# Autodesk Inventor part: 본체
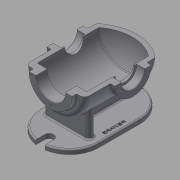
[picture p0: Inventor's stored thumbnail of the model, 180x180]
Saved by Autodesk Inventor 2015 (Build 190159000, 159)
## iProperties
Created: 2016-02
Part Number: 본체
Material: 일반
Document SubType Name: Modeling
Designer: mduedu
Density: 2.71 g/cm^3
Appearance: 기본값
Author: mduedu
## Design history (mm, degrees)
sketch "스케치2"
  geometry: L1 (0, 90)-(0, -90); L2 (65, -65.993)-(65, 90); L3 (65, 90)-(0, 90); A1 r 100 centre (0, 10) between (0, -90) and (65, -65.993); 2 further points
  constraints: 6 end point, 2 point on circle, 1 centre point, 1 coincident, 1 horizontal, 1 midpoint, 1 parallel, 1 point on line, 1 vertical
  dimensions: "d3" = 180 distance of L1.start L1.end; "d5" = 130 diameter of L2 L1; "d6" = 100 radius of A1
revolve "회전1" sketch "스케치2" stored, may be unused: angle "d7" = 90 deg
sketch "스케치3"
  geometry: C1 r 47.5 at (0, 0); 1 further point
  constraints: 1 centre point, 1 coincident
  dimensions: "d8" = 95 diameter of C1
extrude "돌출2" join sketch "스케치3" distance "d10" = 10; taper "d11" = 0 deg
sketch "스케치5"
  geometry: L1 (47.5, 100)-(47.5, 90) reference; L2 (47.5, 90)-(65, 90) reference; L3 (65, 90)-(65, -65.993) reference; L4 (-65, -65.993)-(-65, 90) reference; L5 (-65, 90)-(-47.5, 90) reference; L6 (-47.5, 90)-(-47.5, 100) reference; L7 (-47.5, 100)-(47.5, 100) reference; L8 (55, 75)-(55, -61.239); L9 (0, 75)-(55, 75); L10 (0, 75)-(0, -80); A1 r 100 centre (0, 10) between (-65, -65.993) and (0, -90) reference; A2 r 100 centre (0, 10) between (0, -90) and (65, -65.993) reference; A3 r 90 centre (0, 10) between (0, -80) and (55, -61.239); 1 further point
  constraints: 6 end point, 2 point on circle, 1 centre point, 1 parallel, 1 perpendicular, 1 point on line, 1 vertical
  dimensions: "d13" = 10 distance between parallel lines of L3 L8; "d14" = 10 radial gap between concentric circles of A3 A1; "d15" = 15 distance between parallel lines of L9 L2
revolve "회전2" sketch "스케치5" stored, may be unused: angle "d16" = 90 deg
hole "구멍1" diameter "d19" = 65; stored, may be unused: countersink angle "d23" = 90 deg, drill point angle "d25" = 118 deg; dims "d17" = 10, "d18" = 10, "d20" = 6, "d21" = 4, "d22" = 2, "d24" = 8
node "작업 평면1"
sketch "스케치6"
  geometry: L1 (47.5, 100)-(-47.5, 100) reference; C1 r 40 at (0, -7); 1 further point
  constraints: 1 centre point, 1 vertical alignment
  dimensions: "d27" = 80 diameter of C1; "d29" = 107 distance from line of C1.centre L1
extrude "돌출3" join sketch "스케치6" stored distance "d30" = 10; taper "d31" = 0 deg
hole "구멍2" diameter "d34" = 42; stored, may be unused: countersink angle "d38" = 90 deg, drill point angle "d40" = 118 deg; dims "d32" = 10, "d33" = 10, "d35" = 6, "d36" = 52, "d37" = 18, "d39" = 8
sketch "스케치7" dims "d41" = 65
  geometry: C1 r 40 at (0, 0) reference; 3 further points
  constraints: 2 vertical alignment, 1 coincident, 2 other
hole "구멍3" sketch "스케치7" at (0, 32.5) diameter "d43" = 3.242; stored, may be unused: countersink angle "d47" = 90 deg, drill point angle "d49" = 118 deg; dims "d44" = 11, "d45" = 13, "d46" = 18, "d48" = 13
sketch "스케치8" dims "d53" = 80
  geometry: 3 further points
  constraints: 2 vertical alignment, 1 coincident, 2 other
hole "구멍4" sketch "스케치8" at (0, -40) diameter "d56" = 3.242; stored, may be unused: countersink angle "d60" = 90 deg, drill point angle "d62" = 118 deg; dims "d57" = 11, "d58" = 13, "d59" = 18, "d61" = 13
fillet "모깎기1" dims "d66" = 10
fillet "모깎기2" dims "d67" = 3
fillet "모깎기3" dims "d68" = 0.3
chamfer "모따기1" distance "d69" = 1; stored, may be unused: second distance "d70" = 2, angle "d71" = 45 deg
node "작업 평면5"
sketch "스케치10"
  geometry: L1 (-50, 66)-(50, 66); L2 (50, 66)-(50, 50); L3 (50, 50)-(-50, 50); L4 (-50, 50)-(-50, 66); 2 further points
  constraints: 8 end point, 2 horizontal, 2 vertical, 1 midpoint, 1 vertical alignment
  dimensions: "d177" = 50 distance from line of L3 point (0, 0); "d178" = 100 distance of L1.start L1.end; "d179" = 16 distance of L3.end L1.start
extrude "돌출5" join sketch "스케치10" stored distance "d84" = 10; taper "d85" = 0 deg
sketch "스케치21" dims "d180" = 220, "d182" = 130
  geometry: L1 (65, 58)-(-65, 58); L2 (-65, 58)-(-65, -32); L3 (-65, -32)-(65, -32); L4 (65, -32)-(65, 58); L5 (50, 50)-(50, 66) reference; 4 further points
  constraints: 8 end point, 3 horizontal alignment, 3 midpoint, 2 parallel, 1 horizontal, 1 perpendicular, 1 vertical alignment, 4 other
extrude "돌출13" join sketch "스케치21" distance "d183" = 10; taper "d184" = 0 deg
sketch "스케치11"
  geometry: L1 (-65, 80)-(-65, -61.239) reference; L2 (-100, -97)-(-100, -32) reference; L3 (-65, -42.793)-(-100, -63); L4 (-100, -97)-(-110, -97) reference; 1 further point
  constraints: 2 end point, 2 point on line
  dimensions: "d185" = 34 distance from line of L3.end L4; "d186" = 120 deg angle of L2 L3
feature "리브1" sketch "스케치11" dims "d88" = 1, "d89" = 16, "d90" = 0, "d91" = 0, "d92" = 1, "d93" = 1
fillet "모깎기12"
fillet "모깎기13"
fillet "모깎기16" dims "d167" = 3
fillet "모깎기18"
fillet "모깎기17" dims "d168" = 3
fillet "모깎기19" dims "d187" = 3
node "작업 평면6"
sketch "스케치19"
  geometry: L1 (75, -47)-(75, 33) reference; L2 (-75, -47)-(-75, 33) reference; L3 (75, -7)-(-75, -7); C1 r 22.5 at (0, -7); 1 further point
  constraints: 3 midpoint, 2 end point, 1 centre point
  dimensions: "d149" = 45 diameter of C1
extrude "돌출11" join sketch "스케치19" stored distance "d150" = 10; taper "d151" = 0 deg
hole "구멍6" diameter "d154" = 33.376; stored, may be unused: countersink angle "d158" = 90 deg, drill point angle "d160" = 118 deg; dims "d155" = 6, "d156" = 4, "d157" = 2, "d159" = 8, "d190" = 10, "d191" = 10
fillet "모깎기11" dims "d161" = 3
chamfer "모따기3" distance "d164" = 1; stored, may be unused: second distance "d165" = 2, angle "d166" = 45 deg
node "작업 평면9"
  node "작업 평면8"
sketch "스케치22" dims "d189" = 20
  geometry: L1 (-10, -123)-(10, -123); L2 (10, -123)-(10, -103); L3 (10, -103)-(-10, -103); L4 (-10, -103)-(-10, -123); A1 r 65 centre (0, -58) between (-65, -58) and (65, -58) reference; 2 further points
  constraints: 8 end point, 2 parallel, 1 horizontal, 1 horizontal alignment, 1 midpoint, 1 perpendicular, 1 tangent, 1 vertical alignment, 2 other
  dimensions: "d193" = 30 dimension on L1
extrude "돌출14" cut sketch "스케치22" stored distance "d194" = 10; taper "d195" = 0 deg
fillet "모깎기21" dims "d196" = 3
feature "분할1"
sketch "스케치23"
  geometry: L1 (-65, 32)-(-65, -58) reference; L2 (65, -58)-(65, 32) reference; L3 (-65, -13)-(65, -13); 2 further points
  constraints: 2 end point, 2 midpoint, 1 point on line, 1 other
  dimensions: "d197" = 12 distance from line of point (53, -13) L2
feature "엠보싱2" sketch "스케치23" dims "d8" = 95, "d198" = 0.5, "d199" = 0
node "솔리드2"
pattern_circular "원형 패턴1" dims angle "d51" = 360 deg
mirror "대칭1"
pattern_circular "원형 패턴2" dims angle "d64" = 360 deg
mirror "대칭3"
node "절단 모서리 투영1"
other parameters: "d26" = 75, "d136" = 175
